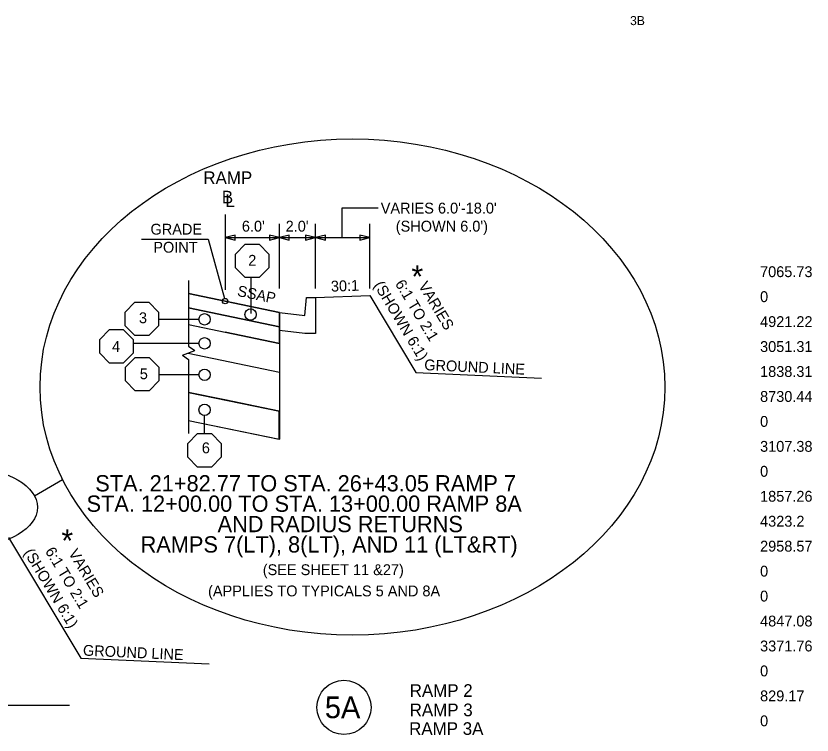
# Model space of a CAD drawing. Extents: x 4932 to 5887, y 4809 to 5473.
# Drawn here: x 5275.5 to 5363.6, y 5135.3 to 5214.8 of the extents above; entities that cross this region are included whole.
import ezdxf

# ---------------------------------------------------------------- set-up
doc = ezdxf.new("R2010")
doc.units = 0
for name, color, linetype in [('Level 25', 7, 'Continuous'), ('RD_QTY_Intermediate', 7, 'Continuous'), ('RD_QTY_Sub_Base', 7, 'Continuous'), ('RD_QTY_Surf_Course', 7, 'Continuous'), ('RD_SHT_TX', 7, 'Continuous'), ('RD_SHT_Typical', 7, 'Continuous'), ('RD_TX_TypSect', 7, 'Continuous'), ('RD_XS_CurbBase', 7, 'Continuous'), ('RD_XS_CurbFront', 7, 'Continuous'), ('RD_XS_CurbTop', 7, 'Continuous'), ('RD_XS_ExGround', 7, 'Continuous'), ('typical_on', 7, 'Continuous')]:
    doc.layers.add(name, color=color, linetype=linetype)

msp = doc.modelspace()

# ---------------------------------------------------------------- linework, layer by layer
at = {"layer": 'Level 25'}
for p, q in [((5294.616, 5184.122), (5304.67, 5182.028)), ((5294.616, 5182.527), (5304.67, 5180.432)), ((5294.616, 5180.7), (5304.67, 5178.606))]:
    msp.add_line(p, q, dxfattribs=at)
msp.add_lwpolyline([(5289.422, 5190.146), (5296.787, 5190.146), (5298.597, 5183.568)], dxfattribs=at)
msp.add_circle((5311.822, 5138.348), 3, dxfattribs=at)
at = {"layer": 'RD_QTY_Intermediate'}
for p, q in [((5294.616, 5182.527), (5294.616, 5180.7)), ((5298.673, 5181.682), (5294.616, 5182.527)), ((5304.67, 5180.432), (5298.673, 5181.682)), ((5294.616, 5180.7), (5298.671, 5179.855)), ((5304.671, 5179.165), (5304.67, 5180.432)), ((5298.671, 5179.855), (5304.67, 5178.606)), ((5304.67, 5178.606), (5304.67, 5180.267)), ((5304.67, 5180.267), (5304.671, 5179.165))]:
    msp.add_line(p, q, dxfattribs=at)
at = {"layer": 'RD_QTY_Sub_Base'}
for p, q in [((5294.616, 5173.19), (5294.616, 5170.091)), ((5298.649, 5172.349), (5294.616, 5173.19)), ((5304.655, 5171.111), (5298.649, 5172.349)), ((5304.649, 5168.012), (5304.655, 5171.111)), ((5294.616, 5170.091), (5304.649, 5168.012))]:
    msp.add_line(p, q, dxfattribs=at)
at = {"layer": 'RD_QTY_Surf_Course'}
for p, q in [((5298.673, 5183.277), (5294.616, 5184.122)), ((5294.616, 5184.122), (5294.616, 5182.527)), ((5304.67, 5182.028), (5298.673, 5183.277)), ((5294.616, 5182.527), (5298.673, 5181.682)), ((5298.673, 5181.682), (5304.67, 5180.432)), ((5304.67, 5180.432), (5304.67, 5182.028))]:
    msp.add_line(p, q, dxfattribs=at)
at = {"layer": 'RD_SHT_Typical'}
for p, q in [((5294.616, 5185.57), (5294.616, 5178.293)), ((5304.67, 5182.028), (5298.673, 5183.277)), ((5308.671, 5183.694), (5314.666, 5183.911)), ((5314.666, 5183.911), (5319.777, 5175.394)), ((5304.67, 5180.432), (5298.649, 5181.673)), ((5304.67, 5182.028), (5304.67, 5167.997)), ((5304.67, 5178.606), (5298.671, 5179.855)), ((5304.67, 5178.606), (5304.67, 5176.354)), ((5294.616, 5176.817), (5294.616, 5168.655)), ((5274.692, 5157.141), (5282.696, 5143.801))]:
    msp.add_line(p, q, dxfattribs=at)
for points in [[(5294.616, 5184.122), (5298.673, 5183.277)], [(5294.616, 5182.527), (5298.673, 5181.682)], [(5294.616, 5180.7), (5298.671, 5179.855)], [(5294.56, 5177.531), (5304.67, 5175.425)], [(5294.616, 5173.19), (5304.67, 5171.095)], [(5294.616, 5170.091), (5304.67, 5167.997)]]:
    msp.add_lwpolyline(points, dxfattribs=at)
at = {"layer": 'RD_TX_TypSect'}
for p, q in [((5298.671, 5192.865), (5298.671, 5184.532)), ((5315.602, 5193.578), (5311.567, 5193.578)), ((5311.567, 5193.578), (5311.567, 5190.315)), ((5304.67, 5184.675), (5304.67, 5191.839)), ((5308.669, 5184.675), (5308.669, 5191.839)), ((5314.666, 5184.675), (5314.666, 5191.839)), ((5298.673, 5190.307), (5304.67, 5190.307)), ((5304.67, 5190.307), (5308.669, 5190.307)), ((5308.669, 5190.307), (5314.666, 5190.307)), ((5301.549, 5181.927), (5301.549, 5185.878)), ((5295.767, 5181.265), (5291.356, 5181.265)), ((5295.767, 5178.611), (5288.479, 5178.611)), ((5293.938, 5177.299), (5295.299, 5177.807)), ((5294.616, 5178.293), (5295.299, 5177.807)), ((5293.938, 5177.299), (5294.616, 5176.817)), ((5295.767, 5175.135), (5291.356, 5175.135)), ((5296.403, 5168.624), (5296.403, 5170.625)), ((5277.561, 5161.741), (5280.672, 5163.568)), ((5223.094, 5138.601), (5281.463, 5138.601))]:
    msp.add_line(p, q, dxfattribs=at)
for points in [[(5299.775, 5190.032), (5299.775, 5190.582), (5298.673, 5190.307)], [(5303.568, 5190.582), (5303.568, 5190.032), (5304.67, 5190.307)], [(5305.773, 5190.032), (5305.773, 5190.582), (5304.67, 5190.307)], [(5307.566, 5190.582), (5307.566, 5190.032), (5308.669, 5190.307)], [(5309.771, 5190.032), (5309.771, 5190.582), (5308.669, 5190.307)], [(5313.564, 5190.582), (5313.564, 5190.032), (5314.666, 5190.307)]]:
    msp.add_lwpolyline(points, close=True, dxfattribs=at)
for centre, radius in [((5298.671, 5183.277), 0.3), ((5301.491, 5181.804), 0.63), ((5296.396, 5181.265), 0.63), ((5296.396, 5178.611), 0.63), ((5296.396, 5175.135), 0.63), ((5296.396, 5171.254), 0.63)]:
    msp.add_circle(centre, radius, dxfattribs=at)
for centre, major_axis, ratio in [((5312.762, 5173.778), (-34.573, 0), 0.793631), ((5270.694, 5160.473), (-7.198, 0), 0.587586)]:
    msp.add_ellipse(centre, major_axis=major_axis, ratio=ratio, dxfattribs=at)
at = {"layer": 'RD_XS_CurbBase'}
for p, q in [((5308.671, 5183.694), (5308.671, 5179.694)), ((5307.504, 5179.694), (5304.67, 5180.028)), ((5308.671, 5179.694), (5307.504, 5179.694))]:
    msp.add_line(p, q, dxfattribs=at)
at = {"layer": 'RD_XS_CurbFront'}
msp.add_line((5304.67, 5182.028), (5304.67, 5180.531), dxfattribs=at)
at = {"layer": 'RD_XS_CurbTop'}
for p, q in [((5307.504, 5181.694), (5307.671, 5183.694)), ((5307.671, 5183.694), (5308.671, 5183.694)), ((5304.67, 5182.028), (5307.504, 5181.694))]:
    msp.add_line(p, q, dxfattribs=at)
at = {"layer": 'RD_XS_ExGround'}
for p, q in [((5319.777, 5175.394), (5333.692, 5174.759)), ((5282.696, 5143.801), (5296.901, 5143.154))]:
    msp.add_line(p, q, dxfattribs=at)
at = {"layer": 'typical_on'}
for points in [[(5303.515, 5188.489), (5303.515, 5186.96), (5302.433, 5185.878), (5300.904, 5185.878), (5299.822, 5186.959), (5299.822, 5188.489), (5300.904, 5189.571), (5302.433, 5189.571)], [(5291.305, 5182.073), (5291.305, 5180.543), (5290.223, 5179.462), (5288.694, 5179.462), (5287.612, 5180.543), (5287.612, 5182.073), (5288.694, 5183.155), (5290.223, 5183.155)], [(5288.479, 5179.042), (5288.479, 5177.513), (5287.398, 5176.431), (5285.868, 5176.431), (5284.787, 5177.512), (5284.787, 5179.042), (5285.868, 5180.124), (5287.398, 5180.124)], [(5291.333, 5175.978), (5291.333, 5174.448), (5290.252, 5173.367), (5288.722, 5173.367), (5287.64, 5174.448), (5287.64, 5175.978), (5288.722, 5177.059), (5290.252, 5177.059)], [(5298.236, 5167.543), (5298.236, 5166.013), (5297.154, 5164.932), (5295.625, 5164.932), (5294.543, 5166.013), (5294.543, 5167.543), (5295.624, 5168.624), (5297.154, 5168.624)]]:
    msp.add_lwpolyline(points, close=True, dxfattribs=at)

# ---------------------------------------------------------------- texts
at = {"layer": 'Level 25'}
for s, height, p in [('RAMP', 1.4, (5296.257, 5196.226)), ('B ', 1.4, (5298.305, 5194.087)), ('GRADE', 1.2, (5290.41, 5190.637)), ('POINT', 1.2, (5290.722, 5188.638)), ('5A', 2.4, (5309.706, 5137.148))]:
    msp.add_text(s, height=height, dxfattribs=at).set_placement(p)
for s, rotation, p in [('SSAP', 348.23191, (5299.941, 5183.868)), ('30:1', 2.06899, (5310.394, 5184.323))]:
    msp.add_text(s, height=1.2, rotation=rotation, dxfattribs=at).set_placement(p)
at = {"layer": 'RD_SHT_TX'}
msp.add_text('3B', height=1, rotation=0.0001, dxfattribs=at).set_placement((5343.482, 5213.811))
at = {"layer": 'RD_TX_TypSect'}
for s, height, p in [('L', 1.4, (5298.693, 5193.701)), ("VARIES 6.0'-18.0'", 1.2, (5315.89, 5192.969)), ("6.0'", 1.2, (5300.523, 5190.969)), ("2.0'", 1.2, (5305.367, 5190.969)), ("(SHOWN 6.0')", 1.2, (5317.551, 5190.969)), ('2', 1.2, (5301.224, 5187.193)), ('*', 2.5, (5319.284, 5184.747)), ('7065.73', 1.2, (5357.867, 5185.934)), ('0', 1.2, (5357.867, 5183.174)), ('3', 1.2, (5289.132, 5180.839)), ('4921.22', 1.2, (5357.867, 5180.414)), ('4', 1.2, (5286.148, 5177.66)), ('3051.31', 1.2, (5357.867, 5177.654)), ('1838.31', 1.2, (5357.867, 5174.894)), ('5', 1.2, (5289.229, 5174.645)), ('8730.44', 1.2, (5357.867, 5172.134)), ('0', 1.2, (5357.867, 5169.374)), ('6', 1.2, (5296.09, 5166.45)), ('3107.38', 1.2, (5357.867, 5166.614)), ('0', 1.2, (5357.867, 5163.854)), ('STA. 21+82.77 TO STA. 26+43.05 RAMP 7', 1.8, (5284.297, 5162.23)), ('1857.26', 1.2, (5357.867, 5161.094)), ('STA. 12+00.00 TO STA. 13+00.00 RAMP 8A', 1.8, (5283.333, 5159.977)), ('AND RADIUS RETURNS', 1.8, (5297.832, 5157.723)), ('4323.2', 1.2, (5357.867, 5158.334)), ('*', 2.5, (5280.548, 5155.538)), ('RAMPS 7(LT), 8(LT), AND 11 (LT&RT)', 1.8, (5289.314, 5155.47)), ('2958.57', 1.2, (5357.867, 5155.574)), ('(SEE SHEET 11 &27)', 1.2, (5302.835, 5152.973)), ('0', 1.2, (5357.867, 5152.814)), ('(APPLIES TO TYPICALS 5 AND 8A ', 1.2, (5296.781, 5150.624)), ('0', 1.2, (5357.867, 5150.054)), ('4847.08', 1.2, (5357.867, 5147.294)), ('3371.76', 1.2, (5357.867, 5144.534)), ('0', 1.2, (5357.867, 5141.774)), ('RAMP 2', 1.4, (5319.092, 5139.509)), ('829.17', 1.2, (5357.867, 5139.014)), ('RAMP 3', 1.4, (5319.092, 5137.365)), ('0', 1.2, (5357.867, 5136.254)), ('RAMP 3A', 1.4, (5319.031, 5135.301))]:
    msp.add_text(s, height=height, dxfattribs=at).set_placement(p)
for s, rotation, p in [('(SHOWN 6:1)', 300.96376, (5315.08, 5185.055)), ('6:1 TO 2:1', 300.96376, (5317.434, 5185.212)), ('VARIES', 300.96376, (5320.01, 5185)), ('GROUND LINE', 357.39046, (5320.686, 5175.65)), ('(SHOWN 6:1)', 300.96376, (5276.354, 5155.471)), ('6:1 TO 2:1', 300.96376, (5278.709, 5155.628)), ('VARIES', 300.96376, (5281.285, 5155.416)), ('GROUND LINE', 357.39046, (5282.916, 5144.074))]:
    msp.add_text(s, height=1.2, rotation=rotation, dxfattribs=at).set_placement(p)

doc.saveas('drawing.dxf')
